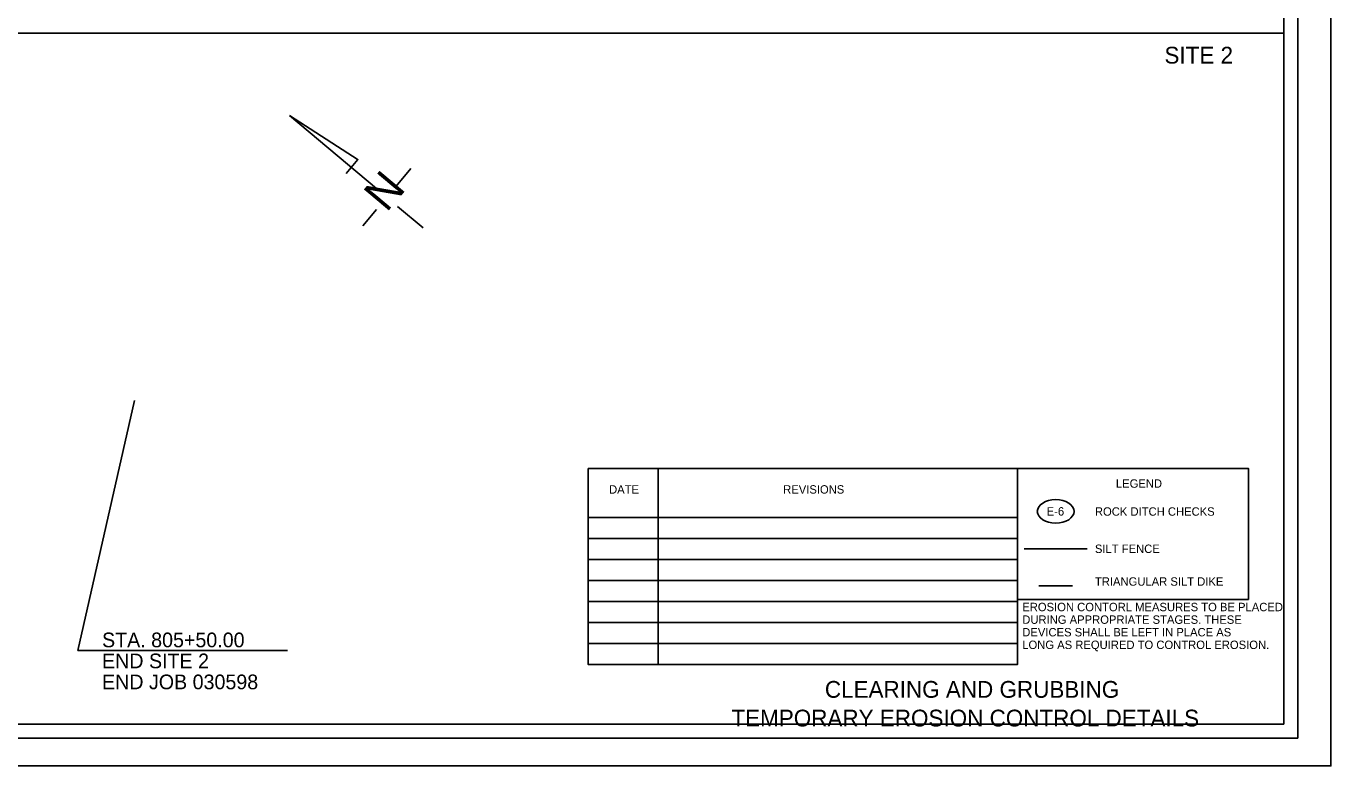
# Model space of a CAD drawing. Extents: x 814841 to 962585, y -174183 to 1802800.
# Drawn here: x 815574 to 816507, y 1801733 to 1802262 of the extents above; entities that cross this region are included whole.
import ezdxf

# ---------------------------------------------------------------- set-up
doc = ezdxf.new("R2010")
doc.units = 0
for name, color, linetype in [('_Silt Dike Legend', 7, 'Continuous'), ('Default', 7, 'Continuous'), ('Legend', 7, 'Continuous'), ('R_Border', 7, 'Continuous'), ('R_Border Notes', 7, 'Continuous'), ('R_Border Title', 7, 'Continuous'), ('R_Detour Annot', 7, 'Continuous'), ('R_Draft', 7, 'Continuous'), ('R_No Plot', 7, 'Continuous')]:
    doc.layers.add(name, color=color, linetype=linetype)

# ---------------------------------------------------------------- blocks, each defined once
blk = doc.blocks.new('E-6')
at = {"layer": 'Default'}
blk.add_ellipse((0, 0), major_axis=(13.15, 0), ratio=0.638788, dxfattribs=at)
blk.add_text('E-6', height=6, dxfattribs=at).set_placement((-6.43, -3))

msp = doc.modelspace()

# ---------------------------------------------------------------- linework, layer by layer
at = {"layer": '_Silt Dike Legend'}
msp.add_line((816298.43, 1801862.13), (816322.43, 1801862.13), dxfattribs=at)
at = {"layer": 'Legend'}
msp.add_line((816288, 1801888.52), (816333.02, 1801888.52), dxfattribs=at)
msp.add_lwpolyline([(816283.24, 1801945.92), (816448.24, 1801945.92), (816448.24, 1801852.39), (816283.24, 1801852.39)], close=True, dxfattribs=at)
at = {"layer": 'R_Border'}
for q in [(816483.49, 1802780.6), (814902.59, 1801753.3)]:
    msp.add_line((816483.49, 1801753.3), q, dxfattribs=at)
at = {"layer": 'R_Border Notes'}
for p, q in [((816026.22, 1801945.92), (816283.24, 1801945.92)), ((816026.22, 1801945.92), (816026.22, 1801805.92)), ((815976.22, 1801910.92), (816283.24, 1801910.92)), ((815976.22, 1801895.92), (816283.24, 1801895.92)), ((815976.22, 1801880.92), (816283.24, 1801880.92)), ((815976.22, 1801865.92), (816283.24, 1801865.92)), ((815976.22, 1801850.92), (816283.24, 1801850.92)), ((815976.22, 1801835.92), (816283.24, 1801835.92)), ((815976.22, 1801820.92), (816283.24, 1801820.92)), ((815976.22, 1801805.92), (816283.24, 1801805.92))]:
    msp.add_line(p, q, dxfattribs=at)
msp.add_lwpolyline([(815976.22, 1801945.92), (816283.24, 1801945.92), (816283.24, 1801805.92), (815976.22, 1801805.92)], close=True, dxfattribs=at)
at = {"layer": 'R_Draft'}
for p, q in [((815762.67, 1802198.16), (815811.92, 1802166.33)), ((815824.99, 1802145.86), (815762.67, 1802198.16)), ((815803.28, 1802156.71), (815811.6, 1802166.61)), ((815838.94, 1802147.56), (815849.53, 1802160.18)), ((815858.41, 1802117.8), (815840.09, 1802133.18)), ((815815.13, 1802119.2), (815825.05, 1802131.02)), ((815611.39, 1801815.89), (815651.95, 1801994.39)), ((815761.39, 1801815.89), (815611.39, 1801815.89))]:
    msp.add_line(p, q, dxfattribs=at)
at = {"layer": 'R_No Plot'}
for points in [[(814840.55, 1802800.08), (816507.25, 1802800.08), (816507.25, 1801733.39), (814840.55, 1801733.39)], [(814912.59, 1802770.6), (816160.29, 1802770.6), (816160.29, 1802721.2), (816247.99, 1802721.2), (816368.49, 1802721.2), (816368.49, 1802609.54), (816473.49, 1802609.54), (816473.49, 1801763.3), (814912.59, 1801763.3)], [(814912.59, 1802256.95), (816473.49, 1802256.95), (816473.49, 1801763.3), (814912.59, 1801763.3)], [(814912.59, 1802256.95), (816473.49, 1802256.95), (816473.49, 1801763.3), (814912.59, 1801763.3)]]:
    msp.add_lwpolyline(points, close=True, dxfattribs=at)

# ---------------------------------------------------------------- block references
at = {"layer": 'Legend', "rotation": -1.8065126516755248e-10}
msp.add_blockref('E-6', (816310.51, 1801915.24), dxfattribs=at)

# ---------------------------------------------------------------- texts
at = {"layer": 'Legend'}
for s, p in [('LEGEND', (816353.55, 1801932.13)), ('DATE', (815991.22, 1801927.92)), ('  REVISIONS', (816111.22, 1801927.92)), ('ROCK DITCH CHECKS', (816338.55, 1801912.13)), ('SILT FENCE', (816338.55, 1801885.52)), ('TRIANGULAR SILT DIKE', (816338.55, 1801862.13)), ('EROSION CONTORL MEASURES TO BE PLACED', (816286.61, 1801843.9)), ('DURING APPROPRIATE STAGES. THESE ', (816286.61, 1801834.9)), ('DEVICES SHALL BE LEFT IN PLACE AS ', (816286.61, 1801825.9)), ('LONG AS REQUIRED TO CONTROL EROSION.', (816286.61, 1801816.9))]:
    msp.add_text(s, height=6, dxfattribs=at).set_placement(p)
at = {"layer": 'R_Border'}
msp.add_text('SITE 2', height=12, dxfattribs=at).set_placement((816388.25, 1802235.17))
at = {"layer": 'R_Border Title'}
for s, p in [('CLEARING AND GRUBBING', (816145.5, 1801782.05)), ('TEMPORARY EROSION CONTROL DETAILS', (816078.68, 1801761.55))]:
    msp.add_text(s, height=12, dxfattribs=at).set_placement(p)
at = {"layer": 'R_Detour Annot'}
for s, p in [('STA. 805+50.00', (815628.77, 1801818.14)), ('END SITE 2', (815628.77, 1801803.14)), ('END JOB 030598', (815628.77, 1801788.14))]:
    msp.add_text(s, height=10.5, dxfattribs=at).set_placement(p)
at = {"layer": 'R_Draft'}
msp.add_text('N', height=23.27, rotation=49.991, dxfattribs=at).set_placement((815832.15, 1802128.33))

doc.saveas('drawing.dxf')
